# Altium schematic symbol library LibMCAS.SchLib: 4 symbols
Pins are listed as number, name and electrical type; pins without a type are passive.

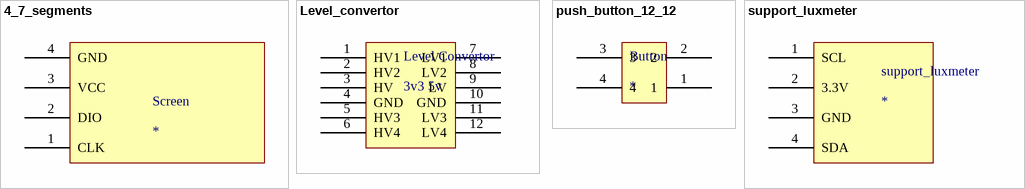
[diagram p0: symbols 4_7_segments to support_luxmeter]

## 4_7_segments
designator Screen
footprint 4_7_segment
pins: 1 CLK, 2 DIO, 3 VCC, 4 GND

## Level_convertor
designator Level Convertor, comment 3v3 5v
footprint level_convertor
pins: 1 HV1, 2 HV2, 3 HV, 4 GND, 5 HV3, 6 HV4, 7 LV1, 8 LV2, 9 LV, 10 GND, 11 LV3, 12 LV4

## push_button_12_12
designator Button
footprint push_button_12_12
pins: 1, 2, 3, 4

## support_luxmeter
designator support_luxmeter
pins: 1 SCL, 2 3.3V, 3 GND, 4 SDA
